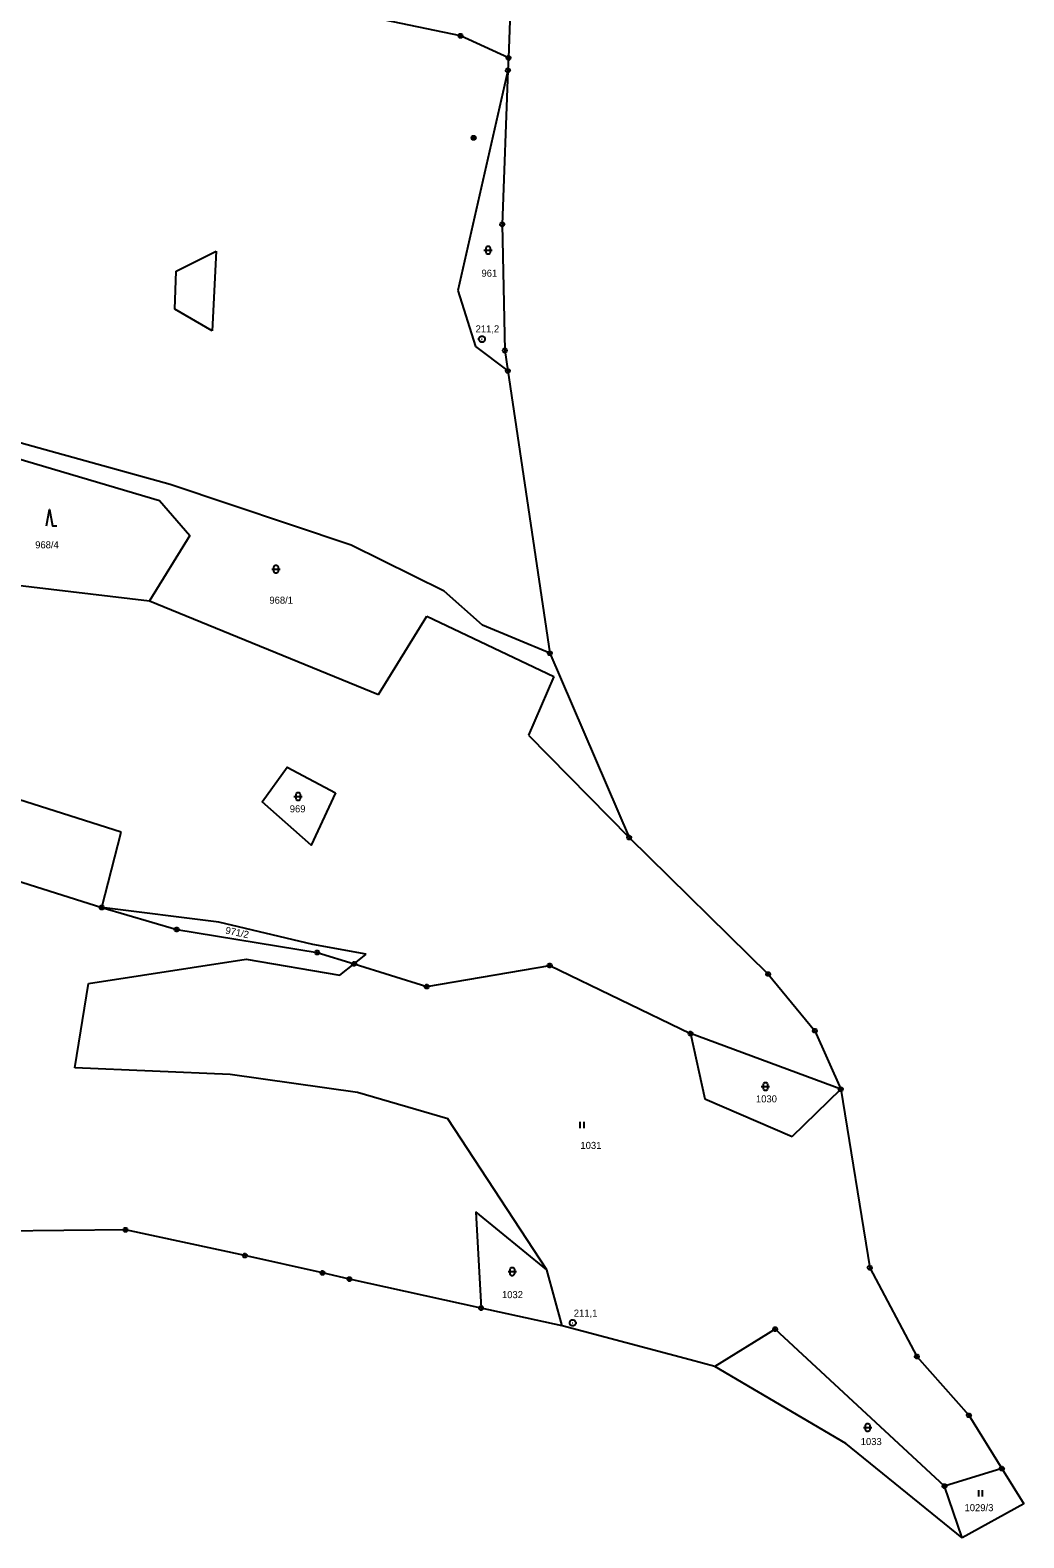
# Model space of a CAD drawing. Extents: x -694465 to -690527, y -983694 to -978978.
# Drawn here: x -690766.8 to -690527.3, y -981760.8 to -981397.2 of the extents above; entities that cross this region are included whole.
import ezdxf

# ---------------------------------------------------------------- set-up
doc = ezdxf.new("R2010")
doc.units = 0
for name, color, linetype in [('Vrstva 1', 7, 'Continuous'), ('Vrstva 17', 7, 'Continuous'), ('Vrstva 18', 7, 'Continuous'), ('Vrstva 24', 7, 'Continuous'), ('Vrstva 25', 7, 'Continuous'), ('Vrstva 26', 7, 'Continuous')]:
    doc.layers.add(name, color=color, linetype=linetype)

msp = doc.modelspace()

# ---------------------------------------------------------------- linework, layer by layer
at = {"layer": 'Vrstva 1'}
for points in [[(-690650.65, -981379.18), (-690651.55, -981403.94)], [(-690663.13, -981398.59), (-690710.23, -981388.72)], [(-690651.55, -981403.94), (-690663.13, -981398.59)], [(-690651.67, -981406.94), (-690663.75, -981460.05)], [(-690651.67, -981406.94), (-690653.04, -981444.08)], [(-690651.55, -981403.94), (-690651.67, -981406.94)], [(-690653.04, -981444.08), (-690652.44, -981474.48), (-690651.71, -981479.42)], [(-690731.64, -981455.38), (-690722.03, -981450.5)], [(-690722.03, -981450.5), (-690722.92, -981469.71)], [(-690731.97, -981464.51), (-690731.64, -981455.38)], [(-690663.75, -981460.05), (-690659.46, -981473.52)], [(-690722.92, -981469.71), (-690731.97, -981464.51)], [(-690733.05, -981506.76), (-690847, -981475.17)], [(-690659.46, -981473.52), (-690651.71, -981479.42)], [(-690651.71, -981479.42), (-690641.6, -981547.51)], [(-690780.44, -981497.4), (-690735.63, -981510.65)], [(-690689.43, -981521.39), (-690733.05, -981506.76)], [(-690735.63, -981510.65), (-690728.37, -981519.09)], [(-690728.37, -981519.09), (-690738.04, -981534.85)], [(-690667.07, -981532.53), (-690689.43, -981521.39)], [(-690801.16, -981527.35), (-690738.04, -981534.85)], [(-690657.81, -981540.69), (-690667.07, -981532.53)], [(-690738.04, -981534.85), (-690682.84, -981557.44)], [(-690682.84, -981557.44), (-690671.22, -981538.52)], [(-690671.22, -981538.52), (-690640.64, -981553.12)], [(-690641.6, -981547.51), (-690657.81, -981540.69)], [(-690641.6, -981547.51), (-690622.47, -981591.94)], [(-690744.9, -981590.64), (-690854.58, -981555.78)], [(-690640.64, -981553.12), (-690646.73, -981567.23)], [(-690646.73, -981567.23), (-690622.47, -981591.94)], [(-690693.26, -981581.13), (-690699.06, -981593.79), (-690710.92, -981583.35), (-690704.89, -981574.93), (-690693.26, -981581.13)], [(-690833.86, -981582.1), (-690749.57, -981608.8)], [(-690749.57, -981608.8), (-690744.9, -981590.64)], [(-690622.47, -981591.94), (-690588.96, -981624.84), (-690577.73, -981638.51), (-690571.48, -981652.64)], [(-690721.34, -981612.33), (-690749.57, -981608.8)], [(-690749.57, -981608.8), (-690731.51, -981614.1)], [(-690731.51, -981614.1), (-690697.67, -981619.66)], [(-690698.67, -981617.7), (-690721.34, -981612.33)], [(-690685.82, -981620.05), (-690698.67, -981617.7)], [(-690752.72, -981627.1), (-690714.79, -981621.26)], [(-690714.79, -981621.26), (-690692.15, -981625.11)], [(-690697.67, -981619.66), (-690688.77, -981622.41)], [(-690688.77, -981622.41), (-690685.82, -981620.05)], [(-690692.15, -981625.11), (-690688.77, -981622.41)], [(-690688.77, -981622.41), (-690671.25, -981627.88)], [(-690671.25, -981627.88), (-690641.62, -981622.79)], [(-690641.62, -981622.79), (-690607.7, -981639.21)], [(-690756.07, -981647.47), (-690752.72, -981627.1)], [(-690607.7, -981639.21), (-690604.24, -981654.91)], [(-690571.48, -981652.64), (-690607.7, -981639.21)], [(-690718.58, -981649.08), (-690756.07, -981647.47)], [(-690687.93, -981653.44), (-690718.58, -981649.08)], [(-690666.13, -981659.8), (-690687.93, -981653.44)], [(-690583.2, -981663.99), (-690571.48, -981652.64)], [(-690571.48, -981652.64), (-690564.49, -981695.68), (-690553.14, -981717.06), (-690540.58, -981731.26), (-690532.62, -981744.11)], [(-690604.24, -981654.91), (-690583.2, -981663.99)], [(-690642.32, -981696.19), (-690666.13, -981659.8)], [(-690658.11, -981705.41), (-690689.89, -981698.41), (-690696.38, -981696.93), (-690715.07, -981692.75), (-690743.85, -981686.53), (-690773.58, -981686.86), (-690797.41, -981677.54)], [(-690642.32, -981696.19), (-690659.44, -981682.16)], [(-690659.44, -981682.16), (-690658.11, -981705.41)], [(-690638.58, -981709.72), (-690642.32, -981696.19)], [(-690638.58, -981709.72), (-690658.11, -981705.41)], [(-690601.81, -981719.45), (-690607.75, -981717.88), (-690638.58, -981709.72)], [(-690587.26, -981710.46), (-690601.81, -981719.45)], [(-690546.45, -981748.33), (-690587.26, -981710.46)], [(-690542.18, -981760.81), (-690570.22, -981738.03), (-690601.81, -981719.45)], [(-690532.62, -981744.11), (-690546.45, -981748.33)], [(-690532.62, -981744.11), (-690527.35, -981752.61)], [(-690542.18, -981760.81), (-690546.45, -981748.33)], [(-690527.35, -981752.61), (-690542.18, -981760.81)]]:
    msp.add_lwpolyline(points, dxfattribs=at)
at = {"layer": 'Vrstva 24'}
for points in [[(-690662.976, -981398.114), (-690662.726, -981398.296), (-690662.63, -981398.59), (-690662.726, -981398.884), (-690662.976, -981399.066), (-690663.284, -981399.066), (-690663.534, -981398.884), (-690663.63, -981398.59), (-690663.534, -981398.296), (-690663.284, -981398.114)], [(-690651.516, -981406.464), (-690651.266, -981406.646), (-690651.17, -981406.94), (-690651.266, -981407.234), (-690651.516, -981407.416), (-690651.824, -981407.416), (-690652.074, -981407.234), (-690652.17, -981406.94), (-690652.074, -981406.646), (-690651.824, -981406.464)], [(-690651.396, -981403.464), (-690651.146, -981403.646), (-690651.05, -981403.94), (-690651.146, -981404.234), (-690651.396, -981404.416), (-690651.704, -981404.416), (-690651.954, -981404.234), (-690652.05, -981403.94), (-690651.954, -981403.646), (-690651.704, -981403.464)], [(-690652.886, -981443.604), (-690652.636, -981443.786), (-690652.54, -981444.08), (-690652.636, -981444.374), (-690652.886, -981444.556), (-690653.194, -981444.556), (-690653.444, -981444.374), (-690653.54, -981444.08), (-690653.444, -981443.786), (-690653.194, -981443.604)], [(-690657.766, -981471.016), (-690657.43, -981471.21), (-690657.236, -981471.546), (-690657.236, -981471.934), (-690657.43, -981472.27), (-690657.766, -981472.464), (-690658.154, -981472.464), (-690658.49, -981472.27), (-690658.684, -981471.934), (-690658.684, -981471.546), (-690658.49, -981471.21), (-690658.154, -981471.016)], [(-690652.286, -981474.004), (-690652.036, -981474.186), (-690651.94, -981474.48), (-690652.036, -981474.774), (-690652.286, -981474.956), (-690652.594, -981474.956), (-690652.844, -981474.774), (-690652.94, -981474.48), (-690652.844, -981474.186), (-690652.594, -981474.004)], [(-690651.556, -981478.944), (-690651.306, -981479.126), (-690651.21, -981479.42), (-690651.306, -981479.714), (-690651.556, -981479.896), (-690651.864, -981479.896), (-690652.114, -981479.714), (-690652.21, -981479.42), (-690652.114, -981479.126), (-690651.864, -981478.944)], [(-690641.446, -981547.034), (-690641.196, -981547.216), (-690641.1, -981547.51), (-690641.196, -981547.804), (-690641.446, -981547.986), (-690641.754, -981547.986), (-690642.004, -981547.804), (-690642.1, -981547.51), (-690642.004, -981547.216), (-690641.754, -981547.034)], [(-690622.316, -981591.464), (-690622.066, -981591.646), (-690621.97, -981591.94), (-690622.066, -981592.234), (-690622.316, -981592.416), (-690622.624, -981592.416), (-690622.874, -981592.234), (-690622.97, -981591.94), (-690622.874, -981591.646), (-690622.624, -981591.464)], [(-690749.416, -981608.324), (-690749.166, -981608.506), (-690749.07, -981608.8), (-690749.166, -981609.094), (-690749.416, -981609.276), (-690749.724, -981609.276), (-690749.974, -981609.094), (-690750.07, -981608.8), (-690749.974, -981608.506), (-690749.724, -981608.324)], [(-690731.356, -981613.624), (-690731.106, -981613.806), (-690731.01, -981614.1), (-690731.106, -981614.394), (-690731.356, -981614.576), (-690731.664, -981614.576), (-690731.914, -981614.394), (-690732.01, -981614.1), (-690731.914, -981613.806), (-690731.664, -981613.624)], [(-690697.516, -981619.184), (-690697.266, -981619.366), (-690697.17, -981619.66), (-690697.266, -981619.954), (-690697.516, -981620.136), (-690697.824, -981620.136), (-690698.074, -981619.954), (-690698.17, -981619.66), (-690698.074, -981619.366), (-690697.824, -981619.184)], [(-690688.616, -981621.934), (-690688.366, -981622.116), (-690688.27, -981622.41), (-690688.366, -981622.704), (-690688.616, -981622.886), (-690688.924, -981622.886), (-690689.174, -981622.704), (-690689.27, -981622.41), (-690689.174, -981622.116), (-690688.924, -981621.934)], [(-690641.466, -981622.314), (-690641.216, -981622.496), (-690641.12, -981622.79), (-690641.216, -981623.084), (-690641.466, -981623.266), (-690641.774, -981623.266), (-690642.024, -981623.084), (-690642.12, -981622.79), (-690642.024, -981622.496), (-690641.774, -981622.314)], [(-690588.806, -981624.364), (-690588.556, -981624.546), (-690588.46, -981624.84), (-690588.556, -981625.134), (-690588.806, -981625.316), (-690589.114, -981625.316), (-690589.364, -981625.134), (-690589.46, -981624.84), (-690589.364, -981624.546), (-690589.114, -981624.364)], [(-690671.096, -981627.404), (-690670.846, -981627.586), (-690670.75, -981627.88), (-690670.846, -981628.174), (-690671.096, -981628.356), (-690671.404, -981628.356), (-690671.654, -981628.174), (-690671.75, -981627.88), (-690671.654, -981627.586), (-690671.404, -981627.404)], [(-690607.546, -981638.734), (-690607.296, -981638.916), (-690607.2, -981639.21), (-690607.296, -981639.504), (-690607.546, -981639.686), (-690607.854, -981639.686), (-690608.104, -981639.504), (-690608.2, -981639.21), (-690608.104, -981638.916), (-690607.854, -981638.734)], [(-690577.576, -981638.034), (-690577.326, -981638.216), (-690577.23, -981638.51), (-690577.326, -981638.804), (-690577.576, -981638.986), (-690577.884, -981638.986), (-690578.134, -981638.804), (-690578.23, -981638.51), (-690578.134, -981638.216), (-690577.884, -981638.034)], [(-690571.326, -981652.164), (-690571.076, -981652.346), (-690570.98, -981652.64), (-690571.076, -981652.934), (-690571.326, -981653.116), (-690571.634, -981653.116), (-690571.884, -981652.934), (-690571.98, -981652.64), (-690571.884, -981652.346), (-690571.634, -981652.164)], [(-690571.326, -981652.164), (-690571.076, -981652.346), (-690570.98, -981652.64), (-690571.076, -981652.934), (-690571.326, -981653.116), (-690571.634, -981653.116), (-690571.884, -981652.934), (-690571.98, -981652.64), (-690571.884, -981652.346), (-690571.634, -981652.164)], [(-690743.696, -981686.054), (-690743.446, -981686.236), (-690743.35, -981686.53), (-690743.446, -981686.824), (-690743.696, -981687.006), (-690744.004, -981687.006), (-690744.254, -981686.824), (-690744.35, -981686.53), (-690744.254, -981686.236), (-690744.004, -981686.054)], [(-690743.696, -981686.054), (-690743.446, -981686.236), (-690743.35, -981686.53), (-690743.446, -981686.824), (-690743.696, -981687.006), (-690744.004, -981687.006), (-690744.254, -981686.824), (-690744.35, -981686.53), (-690744.254, -981686.236), (-690744.004, -981686.054)], [(-690714.916, -981692.274), (-690714.666, -981692.456), (-690714.57, -981692.75), (-690714.666, -981693.044), (-690714.916, -981693.226), (-690715.224, -981693.226), (-690715.474, -981693.044), (-690715.57, -981692.75), (-690715.474, -981692.456), (-690715.224, -981692.274)], [(-690714.916, -981692.274), (-690714.666, -981692.456), (-690714.57, -981692.75), (-690714.666, -981693.044), (-690714.916, -981693.226), (-690715.224, -981693.226), (-690715.474, -981693.044), (-690715.57, -981692.75), (-690715.474, -981692.456), (-690715.224, -981692.274)], [(-690696.226, -981696.454), (-690695.976, -981696.636), (-690695.88, -981696.93), (-690695.976, -981697.224), (-690696.226, -981697.406), (-690696.534, -981697.406), (-690696.784, -981697.224), (-690696.88, -981696.93), (-690696.784, -981696.636), (-690696.534, -981696.454)], [(-690696.226, -981696.454), (-690695.976, -981696.636), (-690695.88, -981696.93), (-690695.976, -981697.224), (-690696.226, -981697.406), (-690696.534, -981697.406), (-690696.784, -981697.224), (-690696.88, -981696.93), (-690696.784, -981696.636), (-690696.534, -981696.454)], [(-690564.336, -981695.204), (-690564.086, -981695.386), (-690563.99, -981695.68), (-690564.086, -981695.974), (-690564.336, -981696.156), (-690564.644, -981696.156), (-690564.894, -981695.974), (-690564.99, -981695.68), (-690564.894, -981695.386), (-690564.644, -981695.204)], [(-690564.336, -981695.204), (-690564.086, -981695.386), (-690563.99, -981695.68), (-690564.086, -981695.974), (-690564.336, -981696.156), (-690564.644, -981696.156), (-690564.894, -981695.974), (-690564.99, -981695.68), (-690564.894, -981695.386), (-690564.644, -981695.204)], [(-690689.736, -981697.934), (-690689.486, -981698.116), (-690689.39, -981698.41), (-690689.486, -981698.704), (-690689.736, -981698.886), (-690690.044, -981698.886), (-690690.294, -981698.704), (-690690.39, -981698.41), (-690690.294, -981698.116), (-690690.044, -981697.934)], [(-690689.736, -981697.934), (-690689.486, -981698.116), (-690689.39, -981698.41), (-690689.486, -981698.704), (-690689.736, -981698.886), (-690690.044, -981698.886), (-690690.294, -981698.704), (-690690.39, -981698.41), (-690690.294, -981698.116), (-690690.044, -981697.934)], [(-690657.956, -981704.934), (-690657.706, -981705.116), (-690657.61, -981705.41), (-690657.706, -981705.704), (-690657.956, -981705.886), (-690658.264, -981705.886), (-690658.514, -981705.704), (-690658.61, -981705.41), (-690658.514, -981705.116), (-690658.264, -981704.934)], [(-690657.956, -981704.934), (-690657.706, -981705.116), (-690657.61, -981705.41), (-690657.706, -981705.704), (-690657.956, -981705.886), (-690658.264, -981705.886), (-690658.514, -981705.704), (-690658.61, -981705.41), (-690658.514, -981705.116), (-690658.264, -981704.934)], [(-690635.856, -981708.256), (-690635.52, -981708.45), (-690635.326, -981708.786), (-690635.326, -981709.174), (-690635.52, -981709.51), (-690635.856, -981709.704), (-690636.244, -981709.704), (-690636.58, -981709.51), (-690636.774, -981709.174), (-690636.774, -981708.786), (-690636.58, -981708.45), (-690636.244, -981708.256)], [(-690587.106, -981709.984), (-690586.856, -981710.166), (-690586.76, -981710.46), (-690586.856, -981710.754), (-690587.106, -981710.936), (-690587.414, -981710.936), (-690587.664, -981710.754), (-690587.76, -981710.46), (-690587.664, -981710.166), (-690587.414, -981709.984)], [(-690552.986, -981716.584), (-690552.736, -981716.766), (-690552.64, -981717.06), (-690552.736, -981717.354), (-690552.986, -981717.536), (-690553.294, -981717.536), (-690553.544, -981717.354), (-690553.64, -981717.06), (-690553.544, -981716.766), (-690553.294, -981716.584)], [(-690552.986, -981716.584), (-690552.736, -981716.766), (-690552.64, -981717.06), (-690552.736, -981717.354), (-690552.986, -981717.536), (-690553.294, -981717.536), (-690553.544, -981717.354), (-690553.64, -981717.06), (-690553.544, -981716.766), (-690553.294, -981716.584)], [(-690540.426, -981730.784), (-690540.176, -981730.966), (-690540.08, -981731.26), (-690540.176, -981731.554), (-690540.426, -981731.736), (-690540.734, -981731.736), (-690540.984, -981731.554), (-690541.08, -981731.26), (-690540.984, -981730.966), (-690540.734, -981730.784)], [(-690540.426, -981730.784), (-690540.176, -981730.966), (-690540.08, -981731.26), (-690540.176, -981731.554), (-690540.426, -981731.736), (-690540.734, -981731.736), (-690540.984, -981731.554), (-690541.08, -981731.26), (-690540.984, -981730.966), (-690540.734, -981730.784)], [(-690532.466, -981743.634), (-690532.216, -981743.816), (-690532.12, -981744.11), (-690532.216, -981744.404), (-690532.466, -981744.586), (-690532.774, -981744.586), (-690533.024, -981744.404), (-690533.12, -981744.11), (-690533.024, -981743.816), (-690532.774, -981743.634)], [(-690532.466, -981743.634), (-690532.216, -981743.816), (-690532.12, -981744.11), (-690532.216, -981744.404), (-690532.466, -981744.586), (-690532.774, -981744.586), (-690533.024, -981744.404), (-690533.12, -981744.11), (-690533.024, -981743.816), (-690532.774, -981743.634)], [(-690546.296, -981747.854), (-690546.046, -981748.036), (-690545.95, -981748.33), (-690546.046, -981748.624), (-690546.296, -981748.806), (-690546.604, -981748.806), (-690546.854, -981748.624), (-690546.95, -981748.33), (-690546.854, -981748.036), (-690546.604, -981747.854)]]:
    msp.add_lwpolyline(points, close=True, dxfattribs=at)
for points in [[(-690663.249, -981398.59), (-690663.01, -981398.59)], [(-690651.789, -981406.94), (-690651.55, -981406.94)], [(-690651.669, -981403.94), (-690651.43, -981403.94)], [(-690653.159, -981444.08), (-690652.92, -981444.08)], [(-690658.01, -981471.74), (-690657.91, -981471.74)], [(-690652.559, -981474.48), (-690652.32, -981474.48)], [(-690651.829, -981479.42), (-690651.59, -981479.42)], [(-690641.719, -981547.51), (-690641.48, -981547.51)], [(-690622.589, -981591.94), (-690622.35, -981591.94)], [(-690749.689, -981608.8), (-690749.45, -981608.8)], [(-690731.629, -981614.1), (-690731.39, -981614.1)], [(-690697.789, -981619.66), (-690697.55, -981619.66)], [(-690688.889, -981622.41), (-690688.65, -981622.41)], [(-690641.739, -981622.79), (-690641.5, -981622.79)], [(-690589.079, -981624.84), (-690588.84, -981624.84)], [(-690671.369, -981627.88), (-690671.13, -981627.88)], [(-690607.819, -981639.21), (-690607.58, -981639.21)], [(-690577.849, -981638.51), (-690577.61, -981638.51)], [(-690571.599, -981652.64), (-690571.36, -981652.64)], [(-690571.599, -981652.64), (-690571.36, -981652.64)], [(-690743.969, -981686.53), (-690743.73, -981686.53)], [(-690743.969, -981686.53), (-690743.73, -981686.53)], [(-690715.189, -981692.75), (-690714.95, -981692.75)], [(-690715.189, -981692.75), (-690714.95, -981692.75)], [(-690696.499, -981696.93), (-690696.26, -981696.93)], [(-690696.499, -981696.93), (-690696.26, -981696.93)], [(-690564.609, -981695.68), (-690564.37, -981695.68)], [(-690564.609, -981695.68), (-690564.37, -981695.68)], [(-690690.009, -981698.41), (-690689.77, -981698.41)], [(-690690.009, -981698.41), (-690689.77, -981698.41)], [(-690658.229, -981705.41), (-690657.99, -981705.41)], [(-690658.229, -981705.41), (-690657.99, -981705.41)], [(-690636.1, -981708.98), (-690636, -981708.98)], [(-690587.379, -981710.46), (-690587.14, -981710.46)], [(-690553.259, -981717.06), (-690553.02, -981717.06)], [(-690553.259, -981717.06), (-690553.02, -981717.06)], [(-690540.699, -981731.26), (-690540.46, -981731.26)], [(-690540.699, -981731.26), (-690540.46, -981731.26)], [(-690532.739, -981744.11), (-690532.5, -981744.11)], [(-690532.739, -981744.11), (-690532.5, -981744.11)], [(-690546.569, -981748.33), (-690546.33, -981748.33)]]:
    msp.add_lwpolyline(points, dxfattribs=at)
at = {"layer": 'Vrstva 25'}
for points in [[(-690657.45, -981450.29), (-690655.45, -981450.29)], [(-690762.9, -981516.79), (-690762.15, -981512.79), (-690761.4, -981516.79), (-690760.4, -981516.79)], [(-690708.57, -981527.2), (-690706.57, -981527.2)], [(-690703.25, -981582.05), (-690701.25, -981582.05)], [(-690590.62, -981651.96), (-690588.62, -981651.96)], [(-690634.33, -981660.5), (-690634.33, -981662)], [(-690633.33, -981662), (-690633.33, -981660.5)], [(-690651.63, -981696.61), (-690649.63, -981696.61)], [(-690565.98, -981734.2), (-690563.98, -981734.2)], [(-690538.29, -981749.33), (-690538.29, -981750.83)], [(-690537.29, -981750.83), (-690537.29, -981749.33)]]:
    msp.add_lwpolyline(points, dxfattribs=at)
for points in [[(-690656.95, -981449.79), (-690656.855, -981449.496), (-690656.605, -981449.314), (-690656.295, -981449.314), (-690656.045, -981449.496), (-690655.95, -981449.79), (-690655.95, -981450.79), (-690656.045, -981451.084), (-690656.295, -981451.266), (-690656.605, -981451.266), (-690656.855, -981451.084), (-690656.95, -981450.79)], [(-690708.07, -981526.7), (-690707.975, -981526.406), (-690707.725, -981526.224), (-690707.415, -981526.224), (-690707.165, -981526.406), (-690707.07, -981526.7), (-690707.07, -981527.7), (-690707.165, -981527.994), (-690707.415, -981528.176), (-690707.725, -981528.176), (-690707.975, -981527.994), (-690708.07, -981527.7)], [(-690702.75, -981581.55), (-690702.655, -981581.256), (-690702.405, -981581.074), (-690702.095, -981581.074), (-690701.845, -981581.256), (-690701.75, -981581.55), (-690701.75, -981582.55), (-690701.845, -981582.844), (-690702.095, -981583.026), (-690702.405, -981583.026), (-690702.655, -981582.844), (-690702.75, -981582.55)], [(-690590.12, -981651.46), (-690590.025, -981651.166), (-690589.775, -981650.984), (-690589.465, -981650.984), (-690589.215, -981651.166), (-690589.12, -981651.46), (-690589.12, -981652.46), (-690589.215, -981652.754), (-690589.465, -981652.936), (-690589.775, -981652.936), (-690590.025, -981652.754), (-690590.12, -981652.46)], [(-690651.13, -981696.11), (-690651.035, -981695.816), (-690650.785, -981695.634), (-690650.475, -981695.634), (-690650.225, -981695.816), (-690650.13, -981696.11), (-690650.13, -981697.11), (-690650.225, -981697.404), (-690650.475, -981697.586), (-690650.785, -981697.586), (-690651.035, -981697.404), (-690651.13, -981697.11)], [(-690565.48, -981733.7), (-690565.385, -981733.406), (-690565.135, -981733.224), (-690564.825, -981733.224), (-690564.575, -981733.406), (-690564.48, -981733.7), (-690564.48, -981734.7), (-690564.575, -981734.994), (-690564.825, -981735.176), (-690565.135, -981735.176), (-690565.385, -981734.994), (-690565.48, -981734.7)]]:
    msp.add_lwpolyline(points, close=True, dxfattribs=at)
at = {"layer": 'Vrstva 26'}
msp.add_lwpolyline([(-690660.105, -981422.734), (-690659.795, -981422.734), (-690659.545, -981422.916), (-690659.45, -981423.21), (-690659.545, -981423.504), (-690659.795, -981423.686), (-690660.105, -981423.686), (-690660.355, -981423.504), (-690660.45, -981423.21), (-690660.355, -981422.916), (-690660.105, -981422.734), (-690660.07, -981422.77), (-690659.83, -981422.77), (-690659.67, -981422.85), (-690660.23, -981422.85), (-690660.31, -981422.93), (-690659.59, -981422.93), (-690659.59, -981423.01), (-690660.31, -981423.01), (-690660.352, -981423.09), (-690659.55, -981423.091), (-690659.51, -981423.17), (-690660.39, -981423.17), (-690660.39, -981423.25), (-690659.51, -981423.25), (-690659.541, -981423.329), (-690660.355, -981423.329), (-690660.349, -981423.41), (-690659.541, -981423.41), (-690659.59, -981423.49), (-690660.31, -981423.49), (-690660.23, -981423.57), (-690659.67, -981423.57), (-690659.778, -981423.649), (-690660.118, -981423.649)], dxfattribs=at)

# ---------------------------------------------------------------- texts
at = {"layer": 'Vrstva 17'}
for s, p in [('211,2', (-690659.473, -981470.11)), ('211,1', (-690635.803, -981707.46))]:
    msp.add_text(s, height=1.7, dxfattribs=at).set_placement(p)
at = {"layer": 'Vrstva 18'}
for s, p in [('961', (-690658.056, -981456.69)), ('968/4', (-690765.61, -981522.19)), ('968/1', (-690709.163, -981535.54)), ('969', (-690704.254, -981585.85)), ('1030', (-690591.906, -981655.8)), ('1031', (-690634.207, -981667.02)), ('1032', (-690653.113, -981703.01)), ('1033', (-690566.656, -981738.44)), ('1029/3', (-690541.642, -981754.38))]:
    msp.add_text(s, height=1.7, dxfattribs=at).set_placement(p)
msp.add_text('971/2', height=1.7, rotation=348.30104, dxfattribs=at).set_placement((-690719.888, -981615.078))

doc.saveas('drawing.dxf')
